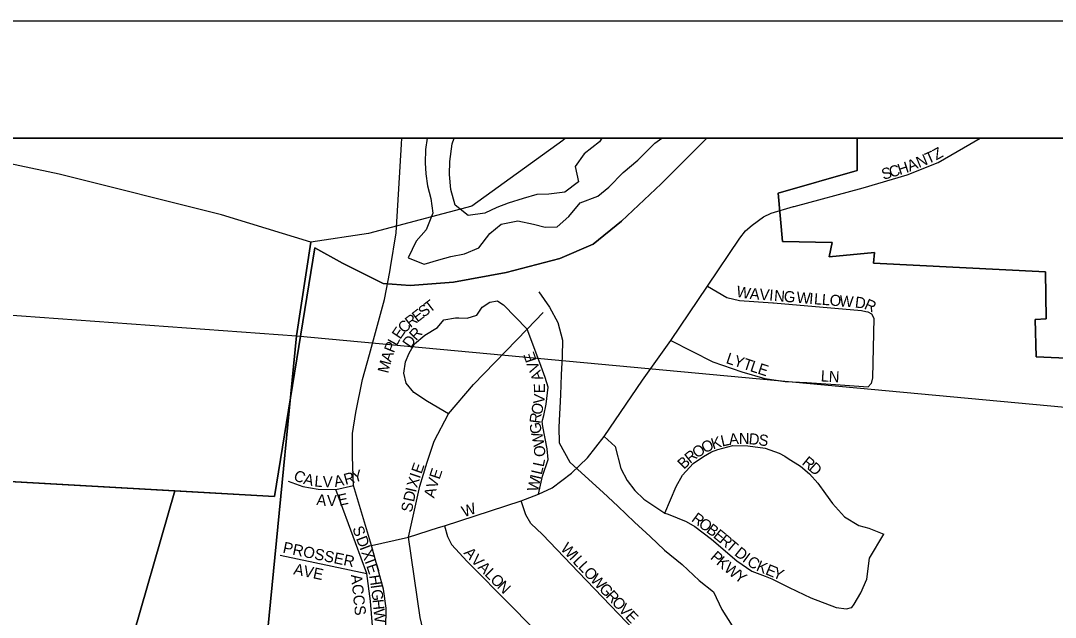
# Model space of a CAD drawing. Extents: x -209 to 4852, y 0 to 905.
# Drawn here: x 536.44 to 554.08, y 330.39 to 340.56 of the extents above; entities that cross this region are included whole.
import ezdxf

# ---------------------------------------------------------------- set-up
doc = ezdxf.new("R2010")
doc.units = 0
for name, color, linetype in [('Default', 7, 'Continuous'), ('GM_X_Airport_Location_Class_2', 7, 'Continuous'), ('GM_X_Airport_Location_Class_3', 7, 'Continuous'), ('GM_X_County_Road', 7, 'Continuous'), ('GM_X_Major_River', 7, 'Continuous'), ('GM_X_Minor_River', 7, 'Continuous'), ('GM_X_US_Location', 7, 'Continuous'), ('SH_Data', 7, 'Continuous')]:
    doc.layers.add(name, color=color, linetype=linetype)

msp = doc.modelspace()

# ---------------------------------------------------------------- linework, layer by layer
at = {"layer": 'Default'}
msp.add_lwpolyline([(571.768, 202.559), (571.768, 338.559), (435.768, 338.559), (435.768, 202.559)], close=True, dxfattribs=at)
at = {"layer": 'GM_X_Airport_Location_Class_2'}
for points in [[(542.749, 336.351), (542.844, 336.944), (542.891, 337.692), (542.938, 338.452), (542.942, 338.559)], [(549.621, 337.392), (549.632, 337.395), (550.807, 337.711), (551.557, 337.93), (552.084, 338.145), (552.518, 338.393), (552.802, 338.559)], [(543.569, 331.919), (543.668, 331.951), (544.979, 332.378), (545.271, 332.487), (545.506, 332.599), (545.836, 332.845), (546.109, 333.109), (546.393, 333.473), (547.043, 334.435), (547.531, 335.108), (548.152, 336.035), (548.705, 336.85), (548.801, 336.975), (548.914, 337.073), (549.108, 337.216), (549.236, 337.278), (549.621, 337.392)], [(540.864, 321.548), (541.196, 322.984), (541.368, 323.781), (541.512, 324.395), (541.657, 325.091), (541.8, 325.815), (542.139, 327.293), (542.418, 328.579), (542.606, 329.677), (542.668, 330.202), (542.673, 330.544), (542.627, 330.87), (542.425, 331.613), (542.119, 332.639), (542.099, 333.13), (542.103, 333.525), (542.156, 333.879), (542.273, 334.441), (542.393, 334.87), (542.647, 335.808), (542.738, 336.281), (542.749, 336.351)], [(548.152, 336.035), (548.483, 335.843), (548.701, 335.791), (549.269, 335.752), (549.278, 335.751)], [(543.913, 335.495), (544.054, 335.489), (544.22, 335.539), (544.31, 335.674), (544.441, 335.764), (544.574, 335.784), (544.631, 335.744)], [(544.631, 335.744), (544.675, 335.714), (545.077, 335.301)], [(549.278, 335.751), (550.777, 335.619), (550.851, 335.605)], [(543.737, 333.861), (543.378, 334.071), (543.145, 334.22), (543.016, 334.383), (542.977, 334.552), (543.005, 334.745), (543.066, 334.891), (543.159, 335.051), (543.336, 335.2), (543.549, 335.332), (543.661, 335.458), (543.858, 335.497), (543.913, 335.495)], [(543.058, 331.759), (543.251, 332.626), (543.375, 333.037), (543.496, 333.393), (543.737, 333.861), (544.166, 334.361), (545.077, 335.301), (545.351, 335.585)], [(550.851, 335.605), (550.885, 335.598), (550.949, 335.563), (550.987, 335.489), (550.966, 334.474), (550.945, 334.374), (550.892, 334.321)], [(545.271, 332.487), (545.341, 332.795), (545.436, 333.08), (545.422, 333.262), (545.344, 333.641), (545.334, 333.729), (545.362, 333.83), (545.404, 334.022), (545.436, 334.311), (545.386, 334.476), (545.292, 334.728), (545.077, 335.301)], [(547.531, 335.108), (548.245, 334.742), (548.739, 334.574), (549.132, 334.462), (549.478, 334.408), (549.844, 334.391), (550.335, 334.356), (550.892, 334.321)], [(546.393, 333.473), (546.577, 333.303), (546.677, 332.926), (546.786, 332.722), (546.916, 332.554), (547.066, 332.403), (547.424, 332.168), (547.481, 332.146)], [(547.424, 332.168), (547.62, 332.62), (547.726, 332.813), (547.908, 333.014), (548.083, 333.129), (548.222, 333.213), (548.332, 333.248), (548.588, 333.318), (548.841, 333.311), (549.137, 333.271), (549.375, 333.187), (549.472, 333.136), (549.529, 333.1)], [(549.529, 333.1), (549.736, 332.968), (549.893, 332.836), (550.035, 332.674), (550.167, 332.494), (550.282, 332.333), (550.489, 332.105), (550.731, 331.958), (550.903, 331.908), (551.162, 331.807)], [(541.005, 332.713), (541.253, 332.618), (541.518, 332.575), (541.815, 332.568), (542.119, 332.639)], [(542.606, 329.677), (542.475, 329.826), (542.408, 330.667), (542.346, 331.138), (542.151, 331.66), (541.815, 332.568)], [(547.46, 329.619), (546.909, 330.167), (545.956, 331.16), (545.34, 331.8), (545.142, 331.99), (545.054, 332.139), (544.979, 332.378)], [(547.481, 332.146), (547.789, 332.024), (547.936, 331.94), (548.222, 331.725), (548.656, 331.354), (548.908, 331.176), (549.139, 331.09)], [(543.003, 331.746), (543.058, 331.759), (543.569, 331.919)], [(543.668, 331.951), (543.723, 331.77), (543.79, 331.632), (544.057, 331.342), (544.814, 330.582), (546.032, 329.334)], [(550.609, 330.558), (550.612, 330.558), (550.655, 330.612), (550.77, 330.807), (550.868, 331.039), (550.917, 331.396), (551.162, 331.807)], [(542.425, 331.613), (543.003, 331.746)], [(543.694, 329.244), (543.608, 329.365), (543.486, 329.587), (543.377, 329.856), (543.322, 330.1), (543.256, 330.387), (543.058, 331.759)], [(540.87, 331.45), (542.346, 331.138)], [(549.139, 331.09), (549.251, 331.049), (549.532, 330.905), (549.677, 330.836)], [(549.677, 330.836), (549.913, 330.723), (550.349, 330.555), (550.524, 330.537), (550.609, 330.558)]]:
    msp.add_lwpolyline(points, dxfattribs=at)
at = {"layer": 'GM_X_County_Road'}
msp.add_lwpolyline([(545.278, 335.938), (545.461, 335.675), (545.599, 335.413), (545.683, 335.115), (545.676, 334.833), (545.661, 334.522), (545.645, 334.18), (545.616, 333.634), (545.625, 333.367), (545.807, 333.036), (546.067, 332.794), (546.372, 332.52), (546.625, 332.286), (546.908, 332.012), (547.175, 331.77), (547.421, 331.536), (547.719, 331.293), (548.009, 331.019), (548.255, 330.823), (548.4, 330.523), (548.576, 330.245)], dxfattribs=at)
at = {"layer": 'GM_X_Major_River'}
for points in [[(543.373, 338.559), (543.345, 338.366), (543.34, 338.138), (543.352, 337.947), (543.378, 337.742), (543.435, 337.527), (543.468, 337.276), (543.356, 336.997), (543.185, 336.802), (543.051, 336.516), (543.322, 336.412), (543.574, 336.483), (543.78, 336.54), (544.008, 336.588), (544.253, 336.69), (544.44, 336.93), (544.633, 337.093), (544.922, 337.148), (545.186, 337.09), (545.383, 337.04), (545.588, 337.044), (545.789, 337.222), (545.983, 337.454), (546.281, 337.57), (546.473, 337.719), (546.714, 337.972), (546.968, 338.18), (547.255, 338.471), (547.376, 338.559)], [(546.349, 338.559), (546.314, 338.497), (546.052, 338.29), (545.896, 338.072), (545.952, 337.812), (545.721, 337.634), (545.447, 337.602), (545.242, 337.598), (545.013, 337.527), (544.753, 337.448), (544.562, 337.376), (544.355, 337.281), (544.074, 337.241), (543.85, 337.413), (543.779, 337.68), (543.754, 337.939), (543.758, 338.16), (543.802, 338.463), (543.835, 338.559)]]:
    msp.add_lwpolyline(points, dxfattribs=at)
at = {"layer": 'GM_X_Minor_River'}
for points in [[(533.673, 338.559), (521.288, 338.559), (521.14, 336.64), (541.147, 335.189), (541.389, 336.783), (539.868, 337.25), (537.101, 337.946), (534.302, 338.536)], [(561.544, 338.559), (545.735, 338.559), (545.686, 338.52), (544.135, 337.398), (542.376, 336.931), (541.389, 336.783), (541.147, 335.189), (561.048, 333.339)], [(521.14, 336.64), (541.147, 335.189), (539.188, 315.131), (519.33, 316.881)], [(541.147, 335.189), (561.048, 333.339), (559.212, 313.354), (558.841, 313.406), (539.664, 315.099), (539.188, 315.131)]]:
    msp.add_lwpolyline(points, close=True, dxfattribs=at)
at = {"layer": 'GM_X_US_Location'}
for points in [[(530.617, 333.026), (540.772, 332.45), (541.459, 336.685), (541.933, 336.429), (542.623, 336.078), (543.085, 336.044), (543.822, 336.102), (544.722, 336.27), (545.638, 336.506), (546.206, 336.751), (546.686, 337.142), (547.361, 337.779), (548.141, 338.559), (527.841, 338.559)], [(530.617, 333.026), (540.772, 332.45), (541.459, 336.685), (541.933, 336.429), (542.623, 336.078), (543.085, 336.044), (543.822, 336.102), (544.722, 336.27), (545.638, 336.506), (546.206, 336.751), (546.686, 337.142), (547.361, 337.779), (548.141, 338.559), (527.841, 338.559)], [(554.657, 334.79), (553.756, 334.828), (553.739, 335.467), (553.929, 335.475), (553.918, 336.281), (550.981, 336.426), (551.002, 336.607), (550.226, 336.534), (550.28, 336.776), (549.431, 336.797), (549.36, 337.62), (550.707, 338.008), (550.705, 338.559), (548.141, 338.559), (547.361, 337.779), (546.686, 337.142), (546.206, 336.751), (545.638, 336.506), (544.722, 336.27), (543.822, 336.102), (543.085, 336.044), (542.623, 336.078), (541.933, 336.429), (541.459, 336.685), (540.772, 332.45), (539.07, 332.547), (538.251, 329.684)], [(554.657, 334.79), (553.756, 334.828), (553.739, 335.467), (553.929, 335.475), (553.918, 336.281), (550.981, 336.426), (551.002, 336.607), (550.226, 336.534), (550.28, 336.776), (549.431, 336.797), (549.36, 337.62), (550.707, 338.008), (550.705, 338.559), (548.141, 338.559), (547.361, 337.779), (546.686, 337.142), (546.206, 336.751), (545.638, 336.506), (544.722, 336.27), (543.822, 336.102), (543.085, 336.044), (542.623, 336.078), (541.933, 336.429), (541.459, 336.685), (540.772, 332.45), (539.07, 332.547), (538.251, 329.684)], [(571.768, 338.559), (550.705, 338.559), (550.707, 338.008), (549.36, 337.62), (549.431, 336.797), (550.28, 336.776), (550.226, 336.534), (551.002, 336.607), (550.981, 336.426), (553.918, 336.281), (553.929, 335.475), (553.739, 335.467), (553.756, 334.828), (554.657, 334.79)], [(538.489, 319.742), (539.206, 324.5), (539.394, 324.477), (539.42, 325.184), (540.192, 325.143), (540.21, 325.7), (539.407, 325.715), (540.047, 328.868), (538.1, 328.907), (538.251, 329.684), (539.07, 332.547), (530.617, 333.026)]]:
    msp.add_lwpolyline(points, dxfattribs=at)
at = {"layer": 'SH_Data'}
for p, q in [((433.768, 340.559), (573.768, 340.559)), ((435.768, 338.559), (571.768, 338.559))]:
    msp.add_line(p, q, dxfattribs=at)

# ---------------------------------------------------------------- texts
at = {"layer": 'GM_X_Airport_Location_Class_3'}
for s, height, rotation, p in [('T', 0.189, 23.7743, (551.914, 338.114)), ('Z', 0.189, 28.8889, (552.053, 338.176)), ('H', 0.189, 18.2634, (551.43, 337.926)), ('A', 0.189, 22.4456, (551.602, 337.984)), ('N', 0.189, 22.8741, (551.758, 338.048)), ('S', 0.189, 16.3695, (551.151, 337.845)), ('C', 0.189, 16.3457, (551.279, 337.882)), ('W', 0.189, 349.6365, (548.634, 335.857)), ('A', 0.189, 355.4206, (548.868, 335.816)), ('V', 0.189, 355.3834, (549.034, 335.803)), ('I', 0.189, 355.3598, (549.2, 335.789)), ('N', 0.189, 355.3756, (549.283, 335.782)), ('G', 0.189, 355.3834, (549.449, 335.769)), ('W', 0.189, 355.3885, (549.665, 335.752)), ('I', 0.189, 355.3598, (549.881, 335.734)), ('L', 0.189, 355.3809, (549.964, 335.727)), ('L', 0.189, 355.3771, (550.097, 335.717)), ('O', 0.189, 355.3874, (550.23, 335.706)), ('W', 0.189, 355.3885, (550.396, 335.692)), ('D', 0.189, 353.4498, (550.66, 335.671)), ('S', 0.189, 37.5662, (543.312, 335.493)), ('T', 0.189, 37.5802, (543.417, 335.574)), ('R', 0.189, 335.7269, (550.811, 335.656)), ('R', 0.189, 37.579, (543.087, 335.32)), ('E', 0.189, 37.5586, (543.206, 335.411)), ('E', 0.189, 55.9235, (542.915, 335.117)), ('C', 0.189, 44.0039, (542.983, 335.219)), ('R', 0.189, 46.614, (543.183, 335.096)), ('L', 0.189, 61.468, (542.854, 335.004)), ('D', 0.189, 55.3339, (543.093, 334.965)), ('P', 0.189, 67.7774, (542.806, 334.885)), ('A', 0.189, 72.3253, (542.757, 334.73)), ('E', 0.189, 108.8065, (545.243, 334.772)), ('L', 0.189, 341.5996, (548.456, 334.727)), ('Y', 0.189, 341.6064, (548.583, 334.685)), ('T', 0.189, 341.6255, (548.741, 334.632)), ('M', 0.189, 75.6987, (542.708, 334.539)), ('V', 0.189, 110.373, (545.301, 334.617)), ('A', 0.189, 109.7313, (545.358, 334.458)), ('L', 0.189, 341.5996, (548.867, 334.59)), ('E', 0.189, 342.222, (548.996, 334.547)), ('L', 0.189, 356.364, (550.08, 334.412)), ('N', 0.189, 357.3401, (550.217, 334.403)), ('E', 0.189, 91.6259, (545.385, 334.212)), ('V', 0.189, 84.4066, (545.368, 334.02)), ('O', 0.189, 75.6191, (545.321, 333.828)), ('R', 0.189, 82.5225, (545.303, 333.685)), ('G', 0.189, 101.0399, (545.334, 333.537)), ('W', 0.189, 101.4249, (545.377, 333.325)), ('O', 0.189, 26.0469, (548.104, 333.182)), ('K', 0.189, 16.693, (548.246, 333.252)), ('L', 0.189, 12.8697, (548.402, 333.299)), ('A', 0.189, 6.0216, (548.526, 333.328)), ('N', 0.189, 359.4098, (548.686, 333.345)), ('D', 0.189, 354.4177, (548.849, 333.343)), ('S', 0.189, 352.2988, (549.013, 333.327)), ('O', 0.189, 93.0262, (545.39, 333.129)), ('R', 0.189, 38.9443, (547.857, 333.003)), ('O', 0.189, 32.8232, (547.969, 333.094)), ('E', 0.189, 70.7009, (543.276, 332.824)), ('L', 0.189, 77.9257, (545.358, 332.944)), ('B', 0.189, 44.0383, (547.752, 332.902)), ('R', 0.189, 320.7106, (549.75, 333.005)), ('D', 0.189, 317.9527, (549.864, 332.912)), ('C', 0.189, 335.2486, (541.079, 332.742)), ('R', 0.189, 15.5138, (541.982, 332.645)), ('Y', 0.189, 15.5291, (542.126, 332.685)), ('I', 0.189, 70.9017, (543.248, 332.745)), ('E', 0.189, 71.6255, (543.585, 332.73)), ('L', 0.189, 77.077, (545.327, 332.811)), ('A', 0.189, 346.4343, (541.253, 332.666)), ('L', 0.189, 355.0373, (541.446, 332.621)), ('V', 0.189, 358.6642, (541.592, 332.609)), ('A', 0.189, 11.0633, (541.803, 332.609)), ('X', 0.189, 73.1898, (543.201, 332.587)), ('V', 0.189, 72.4635, (543.535, 332.571)), ('W', 0.189, 77.081, (545.26, 332.519)), ('I', 0.189, 77.1178, (545.308, 332.73)), ('A', 0.189, 354.0654, (541.48, 332.305)), ('E', 0.189, 11.9349, (541.876, 332.29)), ('D', 0.189, 77.834, (543.148, 332.347)), ('I', 0.189, 77.31, (543.183, 332.51)), ('A', 0.189, 75.5768, (543.494, 332.413)), ('V', 0.189, 359.5536, (541.665, 332.287)), ('S', 0.189, 77.8327, (543.11, 332.168)), ('W', 0.189, 18.424, (544, 332.094)), ('R', 0.189, 323.4993, (547.866, 332.039)), ('O', 0.189, 323.5017, (547.986, 331.95)), ('B', 0.189, 323.0281, (548.12, 331.851)), ('S', 0.189, 290.604, (542.095, 331.906)), ('D', 0.189, 290.62, (542.159, 331.735)), ('E', 0.189, 320.7087, (548.238, 331.762)), ('R', 0.189, 319.8649, (548.341, 331.678)), ('PROSSER', 0.1894, 348.3137, (540.902, 331.495)), ('I', 0.189, 290.5919, (542.218, 331.579)), ('W', 0.189, 313.5733, (545.637, 331.552)), ('T', 0.189, 319.8166, (548.455, 331.581)), ('X', 0.189, 290.6302, (542.247, 331.501)), ('A', 0.189, 311.6136, (543.989, 331.483)), ('V', 0.189, 314.5054, (544.107, 331.351)), ('I', 0.189, 313.5977, (545.786, 331.395)), ('L', 0.189, 313.5896, (545.844, 331.334)), ('P', 0.189, 318.6342, (548.188, 331.396)), ('K', 0.189, 319.4714, (548.291, 331.305)), ('D', 0.189, 321.443, (548.6, 331.459)), ('I', 0.189, 323.0234, (548.735, 331.352)), ('AVE', 0.1894, 348.3109, (541.086, 331.126)), ('I', 0.189, 290.5919, (542.306, 331.345)), ('E', 0.189, 288.0289, (542.334, 331.269)), ('A', 0.189, 314.9992, (544.225, 331.231)), ('L', 0.189, 313.5896, (545.936, 331.238)), ('W', 0.189, 321.2658, (548.422, 331.193)), ('C', 0.189, 326.7315, (548.812, 331.294)), ('K', 0.189, 337.042, (548.971, 331.194)), ('E', 0.189, 337.9476, (549.127, 331.128)), ('Y', 0.189, 337.9266, (549.251, 331.078)), ('ACCS', 0.1894, 276.0051, (542.073, 331.114)), ('H', 0.189, 278.467, (542.385, 331.101)), ('L', 0.189, 315, (544.343, 331.113)), ('O', 0.189, 315, (544.437, 331.018)), ('O', 0.189, 313.578, (546.028, 331.141)), ('W', 0.189, 313.5654, (546.143, 331.02)), ('Y', 0.189, 323.5268, (548.598, 331.052)), ('I', 0.189, 277.7593, (542.409, 330.937)), ('N', 0.189, 315, (544.555, 330.901)), ('G', 0.189, 313.5819, (546.292, 330.863)), ('G', 0.189, 277.5398, (542.42, 330.855)), ('R', 0.189, 313.594, (546.407, 330.743)), ('O', 0.189, 313.578, (546.51, 330.634)), ('H', 0.189, 275.4714, (542.442, 330.691)), ('V', 0.189, 313.5819, (546.625, 330.513)), ('W', 0.189, 275.8914, (542.458, 330.524)), ('E', 0.189, 313.572, (546.74, 330.393))]:
    msp.add_text(s, height=height, rotation=rotation, dxfattribs=at).set_placement(p)

doc.saveas('drawing.dxf')
